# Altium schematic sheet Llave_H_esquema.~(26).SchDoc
size A4
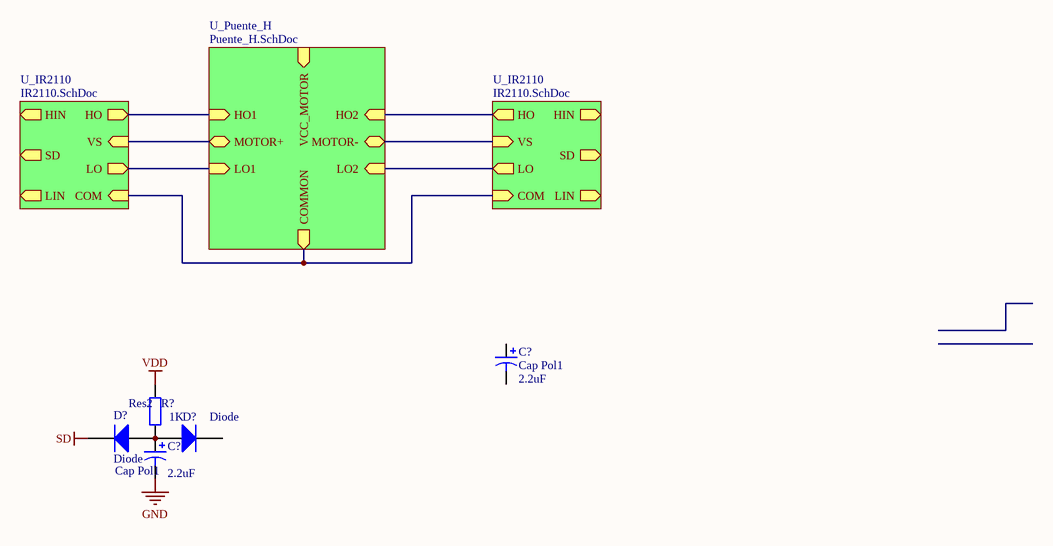
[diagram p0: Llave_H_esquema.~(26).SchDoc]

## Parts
(Parts that share a designator on the sheet are numbered #1, #2 ... from top to bottom, then left to right.)
C?#1  Cap Pol1  value 2.2uF  [RB7.6-15]
C?#2  Cap Pol1  value 2.2uF  [RB7.6-15]
D?#1  Diode  [SMC]
D?#2  Diode  [SMC]
R?  Res2  value 1K  [AXIAL-0.4]

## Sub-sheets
U_IR2110 = IR2110.SchDoc: SD (out), HIN (out), LIN (out), HO (out), LO (out), VS (in), COM (in)
U_IR2110 = IR2110.SchDoc: SD (out), HIN (out), LIN (out), HO (out), LO (out), VS (in), COM (in)
U_Puente_H = Puente_H.SchDoc: HO1 (in), LO1 (in), HO2 (in), LO2 (in), MOTOR+ (bidir), MOTOR- (bidir), VCC_MOTOR (in), COMMON (out)

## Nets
GND: C?#2.2
SD: D?#2.2(K)
VDD: R?.2
NetC?#2_1: C?#2.1 D?#1.1(A) D?#2.1(A) R?.1
(unnamed): sheet U_IR2110/HO, sheet U_Puente_H/HO1
(unnamed): sheet U_IR2110/LO, sheet U_Puente_H/LO1  [a separate net that carries the same name]
(unnamed): sheet U_IR2110/VS, sheet U_Puente_H/MOTOR+  [a separate net that carries the same name]
(unnamed): sheet U_IR2110/COM, sheet U_IR2110/COM, sheet U_Puente_H/COMMON  [a separate net that carries the same name]
(unnamed): sheet U_IR2110/HO, sheet U_Puente_H/HO2  [a separate net that carries the same name]
(unnamed): sheet U_IR2110/LO, sheet U_Puente_H/LO2  [a separate net that carries the same name]
(unnamed): sheet U_IR2110/VS, sheet U_Puente_H/MOTOR-  [a separate net that carries the same name]

Not connected (* = marked no-connect by the designer): C?#1 1 2; D?#1 2(K)

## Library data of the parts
C?#1 C?#2 = Cap Pol1: Polarized Capacitor (Radial)
D?#1 D?#2 = Diode: Default Diode
R? = Res2: Resistor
